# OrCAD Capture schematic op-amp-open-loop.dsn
size A
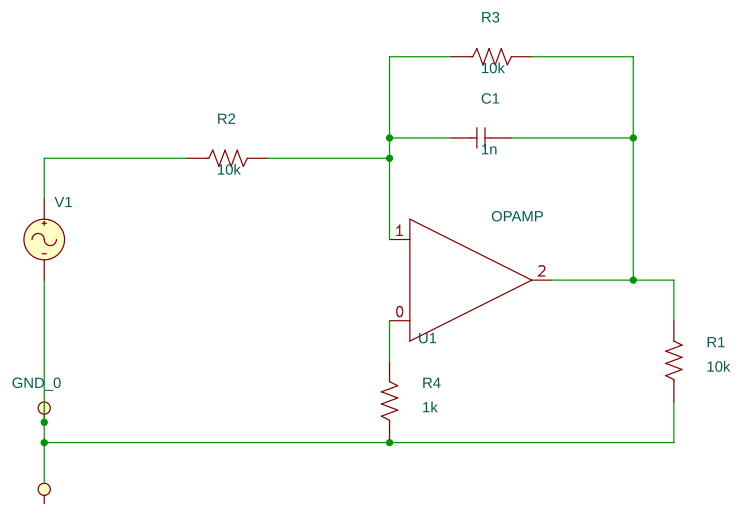
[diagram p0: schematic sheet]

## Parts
C1  1n  [cap196]
R1  10k  [AXRC05]
R2  10k  [AXRC05]
R3  10k  [AXRC05]
R4  1k  [AXRC05]
U1  OPAMP
V1  VAC

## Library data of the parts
C1 = C
R1-R4 = R
U1 = OPAMP
V1 = VAC

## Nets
0: R1.1 R4.1 V1.2(-)
N14369: R2.1 V1.1(+)
N14375: C1.1 R2.2 R3.1 U1.1(-)
N14381: R4.2 U1.0(+)
N14454: C1.2 R1.2 R3.2 U1.2(OUT)
